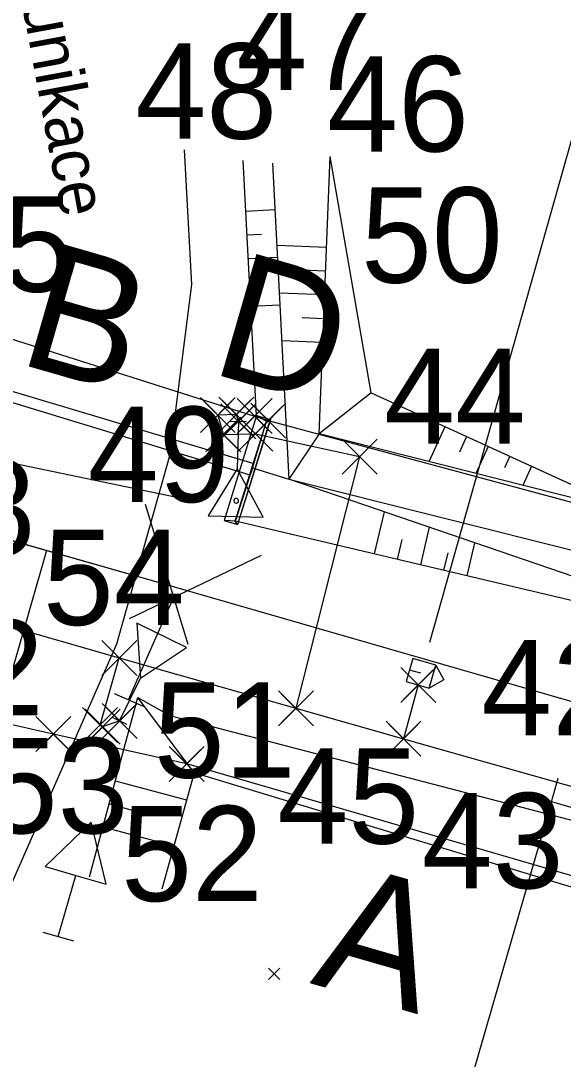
# Model space of a CAD drawing. Extents: x -866402 to -860377, y -1041908 to -1038598.
# Drawn here: x -862091.06 to -862073.97, y -1039288.88 to -1039256.18 of the extents above; entities that cross this region are included whole.
import ezdxf

# ---------------------------------------------------------------- set-up
doc = ezdxf.new("R2010")
doc.units = 0
for name, color, linetype in [('PS 01 prvky', 7, 'Continuous'), ('PS 01 trasa', 7, 'Continuous'), ('PS 02 trasa', 7, 'Continuous'), ('SZDC', 7, 'Continuous'), ('Vrstva 1', 7, 'Continuous'), ('Vrstva 19', 7, 'Continuous'), ('Vrstva 4', 7, 'Continuous'), ('Vrstva 43', 7, 'Continuous'), ('Vrstva 48', 7, 'Continuous'), ('Vrstva 49', 7, 'Continuous'), ('Vrstva 5', 7, 'Continuous'), ('Vrstva 51', 7, 'Continuous'), ('Vrstva 60', 7, 'Continuous')]:
    doc.layers.add(name, color=color, linetype=linetype)

msp = doc.modelspace()

# ---------------------------------------------------------------- linework, layer by layer
at = {"layer": 'PS 01 prvky'}
for p, q in [((-862078.169, -1039275.744), (-862071.017, -1039250.372)), ((-862084.45, -1039268.785), (-862083.95, -1039268.8)), ((-862084.2, -1039268.793), (-862084.243, -1039270.292)), ((-862087.942, -1039278.225), (-862087.28, -1039276.879)), ((-862087.718, -1039278.335), (-862088.166, -1039278.115))]:
    msp.add_line(p, q, dxfattribs=at)
for points in [[(-862084.243, -1039270.292), (-862085.151, -1039271.766), (-862083.42, -1039271.816)], [(-862084.243, -1039270.292), (-862085.151, -1039271.766), (-862083.42, -1039271.816)], [(-862087.28, -1039276.879), (-862085.841, -1039275.915), (-862087.396, -1039275.15)], [(-862077.989, -1039276.471), (-862078.709, -1039276.263), (-862078.917, -1039276.984), (-862078.196, -1039277.192)], [(-862077.989, -1039276.471), (-862078.709, -1039276.263), (-862078.917, -1039276.984), (-862078.196, -1039277.192)]]:
    msp.add_lwpolyline(points, close=True, dxfattribs=at)
for points in [[(-862078.453, -1039276.727), (-862078.813, -1039276.624)], [(-862078.453, -1039276.727), (-862078.813, -1039276.624)], [(-862077.989, -1039276.471), (-862077.732, -1039276.935), (-862078.196, -1039277.192)], [(-862077.989, -1039276.471), (-862077.732, -1039276.935), (-862078.196, -1039277.192)]]:
    msp.add_lwpolyline(points, dxfattribs=at)
for major_axis, start_param, end_param in [((-0.068, 0.0315), 6.279956, 9.428007), ((-0.068, 0.0315), 6.279956, 9.428007), ((0.068, -0.0315), 0.001649, 3.139944), ((0.068, -0.0315), 0.001649, 3.139944)]:
    msp.add_ellipse((-862084.271, -1039271.292), major_axis=major_axis, ratio=0.999997, start_param=start_param, end_param=end_param, dxfattribs=at)
at = {"layer": 'PS 01 trasa'}
for points in [[(-862299.094, -1039226.88), (-862273.285, -1039227.678), (-862248.846, -1039231.2), (-862224.656, -1039236.917), (-862200.639, -1039243.685), (-862176.763, -1039250.512), (-862152.592, -1039257.523), (-862128.569, -1039264.442), (-862103.22, -1039271.846), (-862102.219, -1039272.135), (-862096.536, -1039273.771), (-862095.01, -1039274.211), (-862087.952, -1039276.244), (-862082.392, -1039277.828)], [(-862084.2, -1039268.793), (-862084.266, -1039268.58), (-862084.849, -1039268.596), (-862084.678, -1039269.209), (-862083.664, -1039269.188), (-862080.383, -1039269.906)], [(-862080.383, -1039269.906), (-862082.392, -1039277.828)], [(-862087.942, -1039278.225), (-862088.477, -1039278.409), (-862088.56, -1039278.354), (-862087.952, -1039276.244)], [(-862078.539, -1039277.093), (-862079.002, -1039278.787)], [(-862082.392, -1039277.828), (-862079.002, -1039278.787), (-862057.696, -1039284.818), (-862054.643, -1039285.738), (-862009.617, -1039298.655), (-861985.699, -1039305.583), (-861961.75, -1039312.874), (-861943.016, -1039320.452), (-861938.519, -1039321.88), (-861923.67, -1039329.912), (-861916.69, -1039332.966), (-861895.858, -1039346.596), (-861877.055, -1039362.586), (-861859.765, -1039380.3), (-861844.868, -1039399.824)]]:
    msp.add_lwpolyline(points, dxfattribs=at)
at = {"layer": 'PS 02 trasa'}
msp.add_lwpolyline([(-862224.656, -1039236.917), (-862200.639, -1039243.685), (-862176.763, -1039250.512), (-862152.592, -1039257.523), (-862128.569, -1039264.442), (-862103.22, -1039271.846), (-862102.219, -1039272.135), (-862096.536, -1039273.771), (-862095.01, -1039274.211), (-862087.952, -1039276.244), (-862082.392, -1039277.828), (-862079.002, -1039278.787), (-862057.696, -1039284.818), (-862054.643, -1039285.738), (-862009.617, -1039298.655), (-861985.699, -1039305.583), (-861961.75, -1039312.874)], dxfattribs=at)
at = {"layer": 'SZDC'}
for points in [[(-862234.51, -1039218.03), (-862199.37, -1039224.74), (-862172.78, -1039232.45), (-862122.79, -1039257.25), (-862092.95, -1039265.69), (-862091.86, -1039266.04), (-862083.69, -1039268.63), (-862083.26, -1039268.77), (-862042.87, -1039279.64), (-861979.98, -1039297.59), (-861924.06, -1039317.33), (-861903.27, -1039329.1), (-861871.45, -1039352.97), (-861839.12, -1039385.66), (-861823.12, -1039370.41), (-861814.46, -1039390.55)], [(-861669.39, -1039610.88), (-861739.98, -1039582.51), (-861736.58, -1039570.11), (-861761.11, -1039550.44), (-861785.99, -1039518.1), (-861810.72, -1039466.47), (-861837.37, -1039424.62), (-861848.52, -1039406.82), (-861855.53, -1039393.66), (-861857.34, -1039390.64), (-861896.85, -1039350.33), (-861915.3, -1039338.57), (-861931.91, -1039330.04), (-861947.75, -1039322.96), (-861987.36, -1039308.17), (-862085.83, -1039279.58), (-862090.03, -1039278.64), (-862095.47, -1039277.41), (-862098.88, -1039276.65), (-862122.58, -1039271.04), (-862135.01, -1039264.12), (-862179.78, -1039258.36), (-862197.34, -1039258.12), (-862239.36, -1039240.49)]]:
    msp.add_lwpolyline(points, dxfattribs=at)
at = {"layer": 'Vrstva 1'}
msp.add_lwpolyline([(-862198.472, -1039241.657), (-862174.442, -1039248.589), (-862133.53, -1039260.381), (-862093.175, -1039272.025), (-862086.733, -1039273.859), (-862053.719, -1039283.38), (-862020.312, -1039292.989), (-861982.248, -1039303.969)], dxfattribs=at)
at = {"layer": 'Vrstva 19'}
for p, q in [((-862093.334, -1039267.243), (-862083.713, -1039270.117)), ((-862083.834, -1039270.485), (-862093.434, -1039267.569)), ((-862083.627, -1039268.611), (-862084.655, -1039271.912)), ((-862084.301, -1039271.933), (-862083.314, -1039268.797)), ((-862083.193, -1039268.741), (-862084.233, -1039272.043)), ((-862083.198, -1039268.74), (-862084.229, -1039272.045)), ((-862083.713, -1039270.117), (-862083.315, -1039268.798)), ((-862083.627, -1039268.611), (-862083.198, -1039268.74)), ((-862084.297, -1039271.934), (-862083.834, -1039270.485)), ((-862084.655, -1039271.912), (-862084.229, -1039272.045))]:
    msp.add_line(p, q, dxfattribs=at)
for points in [[(-862083.198, -1039268.74), (-862083.193, -1039268.741), (-862083.314, -1039268.797), (-862083.315, -1039268.798), (-862083.627, -1039268.611)], [(-862084.229, -1039272.045), (-862084.233, -1039272.043), (-862084.301, -1039271.933), (-862084.297, -1039271.934), (-862084.655, -1039271.912)]]:
    msp.add_lwpolyline(points, dxfattribs=at)
msp.add_ellipse((-862083.775, -1039270.303), major_axis=(0.062, 0.186), ratio=0.047334, start_param=3.350057, end_param=6.331734, dxfattribs=at)
at = {"layer": 'Vrstva 4'}
for p, q in [((-862087.136, -1039271.399), (-862085.798, -1039275.81)), ((-862093.175, -1039272.025), (-862086.733, -1039273.859)), ((-862090.242, -1039272.86), (-862106.796, -1039330.326)), ((-862087.629, -1039275.005), (-862083.474, -1039273.008)), ((-862087.659, -1039277.559), (-862086.25, -1039274.355)), ((-862088.117, -1039277.358), (-862087.201, -1039277.76))]:
    msp.add_line(p, q, dxfattribs=at)
at = {"layer": 'Vrstva 43'}
msp.add_line((-862085.439, -1039271.339), (-862094.301, -1039269.5), dxfattribs=at)
at = {"layer": 'Vrstva 48'}
for p, q in [((-862083.966, -1039262.174), (-862083.052, -1039262.126)), ((-862083.926, -1039262.923), (-862083.47, -1039262.899)), ((-862081.424, -1039263.317), (-862082.994, -1039263.253)), ((-862083.887, -1039263.672), (-862082.974, -1039263.624)), ((-862081.455, -1039264.066), (-862082.204, -1039264.036)), ((-862083.848, -1039264.421), (-862083.391, -1039264.397)), ((-862081.485, -1039264.816), (-862082.915, -1039264.757)), ((-862083.808, -1039265.17), (-862082.896, -1039265.122)), ((-862081.516, -1039265.565), (-862082.196, -1039265.537)), ((-862081.546, -1039266.314), (-862082.836, -1039266.262)), ((-862077.699, -1039268.962), (-862078.203, -1039270.065)), ((-862077.017, -1039269.273), (-862077.24, -1039269.762)), ((-862076.335, -1039269.584), (-862076.724, -1039270.438)), ((-862075.652, -1039269.895), (-862075.819, -1039270.26)), ((-862074.97, -1039270.207), (-862075.246, -1039270.811)), ((-862079.919, -1039272.969), (-862079.605, -1039271.641)), ((-862078.459, -1039273.314), (-862078.179, -1039272.13)), ((-862079.189, -1039273.141), (-862079.04, -1039272.513)), ((-862076.999, -1039273.659), (-862076.753, -1039272.619)), ((-862077.729, -1039273.486), (-862077.598, -1039272.93)), ((-862088.079, -1039280.111), (-862085.834, -1039280.715)), ((-862088.273, -1039280.835), (-862087.154, -1039281.136)), ((-862088.468, -1039281.559), (-862086.235, -1039282.16))]:
    msp.add_line(p, q, dxfattribs=at)
at = {"layer": 'Vrstva 49'}
for p, q in [((-862083.627, -1039268.611), (-862084.05, -1039260.577)), ((-862083.129, -1039260.661), (-862082.609, -1039270.61)), ((-862081.663, -1039269.191), (-862081.308, -1039260.459)), ((-862080.025, -1039267.901), (-862081.308, -1039260.459)), ((-862080.025, -1039267.901), (-862081.663, -1039269.191)), ((-862080.025, -1039267.901), (-862071.659, -1039271.717)), ((-862081.663, -1039269.191), (-862082.609, -1039270.61)), ((-862071.659, -1039271.717), (-862081.663, -1039269.191)), ((-862083.756, -1039270.261), (-862082.609, -1039270.61)), ((-862082.609, -1039270.61), (-862072.58, -1039273.132)), ((-862072.817, -1039273.969), (-862082.609, -1039270.61)), ((-862073.404, -1039274.508), (-862084.297, -1039271.934)), ((-862088.892, -1039283.133), (-862087.373, -1039277.489)), ((-862085.598, -1039279.864), (-862087.373, -1039277.489)), ((-862085.598, -1039279.864), (-862086.613, -1039283.524)), ((-862061.056, -1039287.285), (-862085.598, -1039279.864)), ((-862083.25, -1039286.012), (-862082.896, -1039286.366)), ((-862083.25, -1039286.366), (-862082.896, -1039286.012))]:
    msp.add_line(p, q, dxfattribs=at)
for points in [[(-862084.297, -1039271.934), (-862083.834, -1039270.485), (-862083.756, -1039270.261), (-862083.713, -1039270.117), (-862083.315, -1039268.798), (-862083.627, -1039268.611)], [(-862087.373, -1039277.489), (-862086.358, -1039278.054), (-862057.993, -1039285.445)]]:
    msp.add_lwpolyline(points, dxfattribs=at)
at = {"layer": 'Vrstva 5'}
for p, q in [((-862074.139, -1039280.043), (-862074.555, -1039281.485)), ((-862074.347, -1039280.764), (-862090.097, -1039335.334)), ((-862074.347, -1039280.764), (-862071.464, -1039281.595))]:
    msp.add_line(p, q, dxfattribs=at)
at = {"layer": 'Vrstva 51'}
msp.add_line((-862090.358, -1039284.873), (-862089.398, -1039285.151), dxfattribs=at)
for points in [[(-862085.913, -1039260.242), (-862085.679, -1039264.488), (-862086.36, -1039269.85), (-862088.036, -1039275.805), (-862092.909, -1039286.89)], [(-862089.878, -1039285.012), (-862089.324, -1039283.09), (-862088.363, -1039283.367), (-862088.839, -1039281.409), (-862090.285, -1039282.813), (-862089.324, -1039283.09)]]:
    msp.add_lwpolyline(points, dxfattribs=at)
at = {"layer": 'Vrstva 60'}
for p, q in [((-862084.399, -1039269.046), (-862085.399, -1039268.046)), ((-862084.399, -1039268.146), (-862085.399, -1039269.146)), ((-862085.299, -1039269.046), (-862084.299, -1039268.046)), ((-862085.299, -1039268.146), (-862084.299, -1039269.146)), ((-862083.816, -1039269.03), (-862084.816, -1039268.03)), ((-862083.816, -1039268.13), (-862084.816, -1039269.13)), ((-862084.716, -1039269.03), (-862083.716, -1039268.03)), ((-862084.716, -1039268.13), (-862083.716, -1039269.13)), ((-862083.24, -1039269.08), (-862084.24, -1039268.08)), ((-862083.24, -1039268.18), (-862084.24, -1039269.18)), ((-862084.14, -1039269.08), (-862083.14, -1039268.08)), ((-862084.14, -1039268.18), (-862083.14, -1039269.18)), ((-862082.81, -1039269.22), (-862083.81, -1039268.22)), ((-862083.71, -1039269.22), (-862082.71, -1039268.22)), ((-862083.75, -1039269.243), (-862084.75, -1039268.243)), ((-862083.75, -1039268.343), (-862084.75, -1039269.343)), ((-862084.65, -1039269.243), (-862083.65, -1039268.243)), ((-862084.65, -1039268.343), (-862083.65, -1039269.343)), ((-862082.81, -1039268.32), (-862083.81, -1039269.32)), ((-862083.71, -1039268.32), (-862082.71, -1039269.32)), ((-862084.228, -1039269.659), (-862085.228, -1039268.659)), ((-862084.228, -1039268.759), (-862085.228, -1039269.759)), ((-862085.128, -1039269.659), (-862084.128, -1039268.659)), ((-862085.128, -1039268.759), (-862084.128, -1039269.759)), ((-862084.849, -1039268.596), (-862084.849, -1039268.596)), ((-862084.266, -1039268.58), (-862084.266, -1039268.58)), ((-862083.214, -1039269.638), (-862084.214, -1039268.638)), ((-862083.214, -1039268.738), (-862084.214, -1039269.738)), ((-862084.2, -1039268.793), (-862084.2, -1039268.793)), ((-862084.114, -1039269.638), (-862083.114, -1039268.638)), ((-862084.114, -1039268.738), (-862083.114, -1039269.738)), ((-862083.69, -1039268.63), (-862083.69, -1039268.63)), ((-862083.26, -1039268.77), (-862083.26, -1039268.77)), ((-862083.664, -1039269.188), (-862083.664, -1039269.188)), ((-862084.678, -1039269.209), (-862084.678, -1039269.209)), ((-862079.933, -1039270.356), (-862080.933, -1039269.356)), ((-862079.933, -1039269.456), (-862080.933, -1039270.456)), ((-862080.833, -1039270.356), (-862079.833, -1039269.356)), ((-862080.833, -1039269.456), (-862079.833, -1039270.456)), ((-862080.383, -1039269.906), (-862080.383, -1039269.906)), ((-862087.502, -1039276.694), (-862088.502, -1039275.694)), ((-862088.402, -1039276.694), (-862087.402, -1039275.694)), ((-862087.502, -1039275.794), (-862088.502, -1039276.794)), ((-862088.402, -1039275.794), (-862087.402, -1039276.794)), ((-862087.952, -1039276.244), (-862087.952, -1039276.244)), ((-862078.089, -1039277.543), (-862079.089, -1039276.543)), ((-862078.089, -1039276.643), (-862079.089, -1039277.643)), ((-862078.989, -1039277.543), (-862077.989, -1039276.543)), ((-862078.989, -1039276.643), (-862077.989, -1039277.643)), ((-862081.942, -1039278.278), (-862082.942, -1039277.278)), ((-862082.842, -1039278.278), (-862081.842, -1039277.278)), ((-862078.539, -1039277.093), (-862078.539, -1039277.093)), ((-862087.492, -1039278.675), (-862088.492, -1039277.675)), ((-862088.392, -1039278.675), (-862087.392, -1039277.675)), ((-862081.942, -1039277.378), (-862082.942, -1039278.378)), ((-862082.842, -1039277.378), (-862081.842, -1039278.378)), ((-862088.11, -1039278.804), (-862089.11, -1039277.804)), ((-862088.11, -1039277.904), (-862089.11, -1039278.904)), ((-862088.027, -1039278.859), (-862089.027, -1039277.859)), ((-862088.027, -1039277.959), (-862089.027, -1039278.959)), ((-862089.01, -1039278.804), (-862088.01, -1039277.804)), ((-862089.01, -1039277.904), (-862088.01, -1039278.904)), ((-862088.927, -1039278.859), (-862087.927, -1039277.859)), ((-862088.927, -1039277.959), (-862087.927, -1039278.959)), ((-862087.492, -1039277.775), (-862088.492, -1039278.775)), ((-862088.392, -1039277.775), (-862087.392, -1039278.775)), ((-862082.392, -1039277.828), (-862082.392, -1039277.828)), ((-862089.58, -1039279.09), (-862090.58, -1039278.09)), ((-862089.58, -1039278.19), (-862090.58, -1039279.19)), ((-862090.48, -1039279.09), (-862089.48, -1039278.09)), ((-862090.48, -1039278.19), (-862089.48, -1039279.19)), ((-862088.56, -1039278.354), (-862088.56, -1039278.354)), ((-862087.942, -1039278.225), (-862087.942, -1039278.225)), ((-862078.552, -1039279.237), (-862079.552, -1039278.237)), ((-862078.552, -1039278.337), (-862079.552, -1039279.337)), ((-862079.452, -1039279.237), (-862078.452, -1039278.237)), ((-862079.452, -1039278.337), (-862078.452, -1039279.337)), ((-862090.03, -1039278.64), (-862090.03, -1039278.64)), ((-862088.477, -1039278.409), (-862088.477, -1039278.409)), ((-862079.002, -1039278.787), (-862079.002, -1039278.787)), ((-862085.38, -1039280.03), (-862086.38, -1039279.03)), ((-862085.38, -1039279.13), (-862086.38, -1039280.13)), ((-862086.28, -1039280.03), (-862085.28, -1039279.03)), ((-862086.28, -1039279.13), (-862085.28, -1039280.13)), ((-862085.83, -1039279.58), (-862085.83, -1039279.58))]:
    msp.add_line(p, q, dxfattribs=at)

# ---------------------------------------------------------------- texts
at = {"layer": 'PS 01 prvky'}
for s, p in [('B', (-862091.222, -1039266.944)), ('D', (-862085.163, -1039267.247)), ('A', (-862081.971, -1039286.476))]:
    msp.add_text(s, height=4, rotation=343.8968, dxfattribs=at).set_placement(p)
at = {"layer": 'Vrstva 51'}
msp.add_text('komunikace', height=1.5, rotation=280.4309, dxfattribs=at).set_placement((-862091.704, -1039251.905))
at = {"layer": 'Vrstva 60'}
for s, p in [('47', (-862084.265, -1039258.362)), ('48', (-862087.445, -1039259.895)), ('46', (-862081.405, -1039260.299)), ('50', (-862080.34, -1039264.429)), ('55', (-862093.858, -1039264.715)), ('44', (-862079.613, -1039269.501)), ('49', (-862088.942, -1039271.335)), ('58', (-862095.057, -1039273.013)), ('54', (-862090.357, -1039275.205)), ('62', (-862094.794, -1039278.048)), ('42', (-862076.551, -1039278.679)), ('51', (-862086.868, -1039280.011)), ('53', (-862092.124, -1039281.763)), ('45', (-862082.97, -1039282.089)), ('43', (-862078.425, -1039283.494)), ('52', (-862087.895, -1039283.899))]:
    msp.add_text(s, height=3, dxfattribs=at).set_placement(p)

doc.saveas('drawing.dxf')
